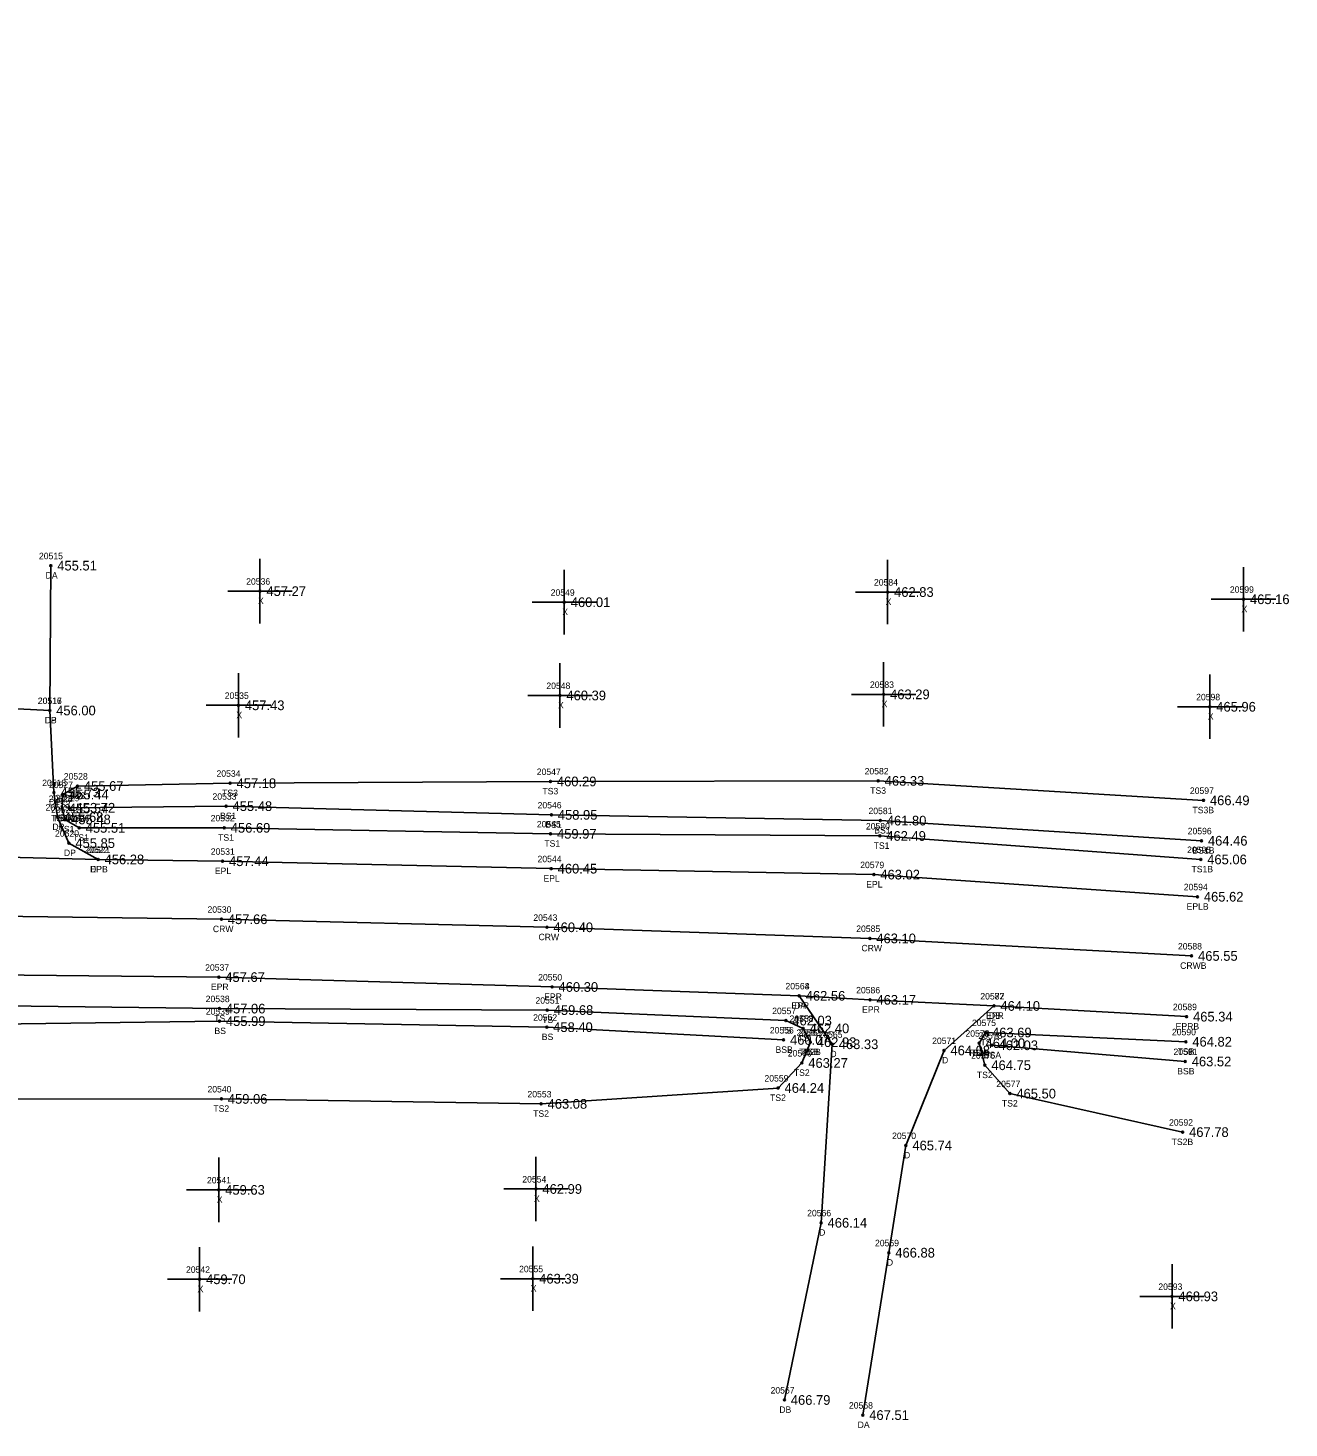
# Model space of a CAD drawing. Extents: x 1810114 to 1811498, y 790790 to 791824.
# Drawn here: x 1811302.7 to 1811498.2, y 791065.8 to 791282.8 of the extents above; entities that cross this region are included whole.
import ezdxf

# ---------------------------------------------------------------- set-up
doc = ezdxf.new("R2010")
doc.units = 0
for name, color, linetype in [('RD_DTM_BkLn1', 7, 'Continuous'), ('RD_DTM_BkLn2', 7, 'Continuous'), ('RD_DTM_BkLn_txCode', 7, 'Continuous'), ('RD_EX_Driveway', 7, 'Continuous'), ('RD_EX_Driveway_txCode', 7, 'Continuous'), ('RD_EX_Misc', 7, 'Continuous'), ('RD_EX_Misc_txCode', 7, 'Continuous'), ('RD_EX_Road', 7, 'Continuous'), ('RD_EX_Road_txCode', 7, 'Continuous'), ('RD_EX_TX_Driveway_ELEV', 7, 'Continuous'), ('RD_EX_TX_Misc_ELEV', 7, 'Continuous'), ('RD_EX_TX_Road_ELEV', 7, 'Continuous'), ('RD_HC_Survey_ELEV', 7, 'Continuous'), ('RD_HC_Survey_txCode', 7, 'Continuous'), ('RD_SMD_Locator', 7, 'Continuous')]:
    doc.layers.add(name, color=color, linetype=linetype)

msp = doc.modelspace()

# ---------------------------------------------------------------- linework, layer by layer
at = {"layer": 'RD_DTM_BkLn1'}
msp.add_lwpolyline([(1810803.51, 791274.51), (1810847.74, 791252.12), (1810893.26, 791230.1), (1810939.59, 791211.03), (1810986.75, 791193.39), (1811034.36, 791179.34), (1811083.17, 791167.31), (1811132.79, 791157.79), (1811182.67, 791151.51), (1811232.87, 791147.29), (1811282.59, 791145.39), (1811332.65, 791144.69), (1811383.13, 791143.44), (1811433.19, 791141.72), (1811483.07, 791139)], dxfattribs=at)
at = {"layer": 'RD_DTM_BkLn2'}
msp.add_line((1811452.12, 791125.15), (1811482.09, 791122.64), dxfattribs=at)
for points in [[(1811307.98, 791161.87), (1811308.04, 791164.02), (1811310.33, 791165.34), (1811334, 791165.77), (1811383.66, 791166.05), (1811434.49, 791166.14), (1811484.91, 791163.12)], [(1811307.98, 791161.87), (1811308.36, 791160.16), (1811310.61, 791158.85), (1811333.1, 791158.86), (1811383.68, 791157.93), (1811434.73, 791157.6), (1811484.49, 791153.96)], [(1811309.04, 791161.97), (1811333.38, 791162.22), (1811383.81, 791160.87), (1811434.81, 791159.98), (1811484.6, 791156.86)], [(1811170.77, 791135.26), (1811171.82, 791137.38), (1811175.07, 791138.52), (1811182.87, 791137.68), (1811232.22, 791132.55), (1811282.26, 791131.47), (1811332.33, 791130.84), (1811383.17, 791130.61), (1811420.16, 791128.98), (1811422.85, 791127.77), (1811423.96, 791125.63)], [(1811170.77, 791135.26), (1811170.4, 791132.25), (1811177.63, 791120.55), (1811182.15, 791120.82), (1811231.43, 791118.77), (1811282.72, 791116.78), (1811332.65, 791116.84), (1811382.22, 791116.07), (1811418.96, 791118.53), (1811422.64, 791122.41), (1811423.96, 791125.63)], [(1811172.12, 791135.15), (1811182.75, 791134.11), (1811232.21, 791129.55), (1811282.34, 791128.2), (1811332.35, 791128.89), (1811383.09, 791127.96), (1811419.81, 791125.98)], [(1811450.12, 791125.48), (1811451.13, 791127.13), (1811482.18, 791125.7)], [(1811450.12, 791125.48), (1811451.02, 791122.06), (1811454.9, 791117.66), (1811481.68, 791111.69)]]:
    msp.add_lwpolyline(points, dxfattribs=at)
at = {"layer": 'RD_EX_Driveway'}
msp.add_line((1811306.2, 791199.5), (1811306.03, 791177.05), dxfattribs=at)
for points in [[(1811285.25, 791154.67), (1811289.79, 791158.28), (1811291.76, 791160.78), (1811292, 791162.12), (1811291.93, 791177.79), (1811306.03, 791177.05), (1811306.69, 791164.33), (1811307.22, 791160.52), (1811309.01, 791156.49), (1811313.54, 791153.96)], [(1811422.24, 791132.82), (1811427.36, 791125.31), (1811425.63, 791097.64), (1811419.93, 791070.17)], [(1811432.09, 791067.83), (1811436.13, 791093), (1811438.78, 791109.62), (1811444.68, 791124.35), (1811452.43, 791131.25)]]:
    msp.add_lwpolyline(points, dxfattribs=at)
at = {"layer": 'RD_EX_Misc'}
for p, q in [((1811338.63, 791190.55), (1811338.63, 791200.55)), ((1811435.94, 791190.41), (1811435.94, 791200.41)), ((1811385.81, 791188.83), (1811385.81, 791198.83)), ((1811491.12, 791189.29), (1811491.12, 791199.29)), ((1811333.63, 791195.55), (1811343.63, 791195.55)), ((1811380.81, 791193.83), (1811390.81, 791193.83)), ((1811430.94, 791195.41), (1811440.94, 791195.41)), ((1811486.12, 791194.29), (1811496.12, 791194.29)), ((1811335.29, 791172.85), (1811335.29, 791182.85)), ((1811385.14, 791174.38), (1811385.14, 791184.38)), ((1811435.32, 791174.55), (1811435.32, 791184.55)), ((1811485.89, 791172.63), (1811485.89, 791182.63)), ((1811380.14, 791179.38), (1811390.14, 791179.38)), ((1811430.32, 791179.55), (1811440.32, 791179.55)), ((1811330.29, 791177.85), (1811340.29, 791177.85)), ((1811480.89, 791177.63), (1811490.89, 791177.63)), ((1811332.24, 791097.74), (1811332.24, 791107.74)), ((1811381.42, 791097.88), (1811381.42, 791107.88)), ((1811327.24, 791102.74), (1811337.24, 791102.74)), ((1811376.42, 791102.88), (1811386.42, 791102.88)), ((1811329.27, 791083.88), (1811329.27, 791093.88)), ((1811380.92, 791083.97), (1811380.92, 791093.97)), ((1811480.03, 791081.23), (1811480.03, 791091.23)), ((1811324.27, 791088.88), (1811334.27, 791088.88)), ((1811375.92, 791088.97), (1811385.92, 791088.97)), ((1811475.03, 791086.23), (1811485.03, 791086.23))]:
    msp.add_line(p, q, dxfattribs=at)
at = {"layer": 'RD_EX_Road'}
for points in [[(1810807.88, 791282.84), (1810852, 791259.68), (1810897.52, 791238.67), (1810942.78, 791219.24), (1810989.92, 791202.01), (1811037.03, 791187.9), (1811084.94, 791176.28), (1811134.78, 791167.28), (1811183.92, 791161.02), (1811232.9, 791156.58), (1811282.68, 791154.92), (1811285.25, 791154.67), (1811313.54, 791153.96), (1811332.83, 791153.68), (1811383.78, 791152.53), (1811433.81, 791151.61), (1811483.97, 791148.18)], [(1810799.46, 791266.97), (1810843.53, 791244.35), (1810889.8, 791222.88), (1810936.32, 791202.72), (1810983.79, 791185.28), (1811031.51, 791170.21), (1811081.62, 791158.02), (1811131.99, 791148.92), (1811148.3, 791146.24), (1811177.02, 791142.75), (1811182.52, 791142.23), (1811232.71, 791137.62), (1811281.86, 791136.25), (1811332.25, 791135.72), (1811383.92, 791134.19), (1811422.24, 791132.82), (1811433.21, 791132.2), (1811452.43, 791131.25), (1811482.29, 791129.59)]]:
    msp.add_lwpolyline(points, dxfattribs=at)
at = {"layer": 'RD_SMD_Locator'}
for centre in [(1811306.2, 791199.5), (1811338.63, 791195.55), (1811385.81, 791193.83), (1811435.94, 791195.41), (1811491.12, 791194.29), (1811385.14, 791179.38), (1811435.32, 791179.55), (1811306.03, 791177.05), (1811306.03, 791177.05), (1811335.29, 791177.85), (1811485.89, 791177.63), (1811310.33, 791165.34), (1811334, 791165.77), (1811383.66, 791166.05), (1811434.49, 791166.14), (1811306.69, 791164.33), (1811308.04, 791164.02), (1811307.98, 791161.87), (1811307.98, 791161.87), (1811309.04, 791161.97), (1811333.38, 791162.22), (1811484.91, 791163.12), (1811307.22, 791160.52), (1811308.36, 791160.16), (1811310.61, 791158.85), (1811333.1, 791158.86), (1811383.81, 791160.87), (1811434.81, 791159.98), (1811383.68, 791157.93), (1811434.73, 791157.6), (1811484.6, 791156.86), (1811309.01, 791156.49), (1811313.54, 791153.96), (1811313.54, 791153.96), (1811332.83, 791153.68), (1811383.78, 791152.53), (1811484.49, 791153.96), (1811433.81, 791151.61), (1811483.97, 791148.18), (1811332.65, 791144.69), (1811383.13, 791143.44), (1811433.19, 791141.72), (1811483.07, 791139), (1811332.25, 791135.72), (1811383.92, 791134.19), (1811422.24, 791132.82), (1811422.24, 791132.82), (1811332.33, 791130.84), (1811383.17, 791130.61), (1811433.21, 791132.2), (1811452.43, 791131.25), (1811452.43, 791131.25), (1811332.35, 791128.89), (1811420.16, 791128.98), (1811482.29, 791129.59), (1811383.09, 791127.96), (1811422.85, 791127.77), (1811451.13, 791127.13), (1811419.81, 791125.98), (1811423.96, 791125.63), (1811423.96, 791125.63), (1811427.36, 791125.31), (1811444.68, 791124.35), (1811450.12, 791125.48), (1811450.12, 791125.48), (1811452.12, 791125.15), (1811482.18, 791125.7), (1811422.64, 791122.41), (1811451.02, 791122.06), (1811482.09, 791122.64), (1811418.96, 791118.53), (1811454.9, 791117.66), (1811332.65, 791116.84), (1811382.22, 791116.07), (1811481.68, 791111.69), (1811438.78, 791109.62), (1811332.24, 791102.74), (1811381.42, 791102.88), (1811425.63, 791097.64), (1811436.13, 791093), (1811329.27, 791088.88), (1811380.92, 791088.97), (1811480.03, 791086.23), (1811419.93, 791070.17), (1811432.09, 791067.83)]:
    msp.add_circle(centre, 0.15, dxfattribs=at)

# ---------------------------------------------------------------- texts
at = {"layer": 'RD_DTM_BkLn_txCode'}
for s, p in [('20534', (1811331.89, 791166.77)), ('20547', (1811381.54, 791167.05)), ('20582', (1811432.37, 791167.14)), ('20527', (1811305.92, 791165.02)), ('20528', (1811308.21, 791166.34)), ('20523', (1811305.87, 791162.87)), ('20524', (1811305.87, 791162.87)), ('20529', (1811306.92, 791162.97)), ('TS3', (1811309.09, 791163.34)), ('20533', (1811331.27, 791163.22)), ('TS3', (1811332.76, 791163.77)), ('TS3', (1811382.42, 791164.05)), ('TS3', (1811433.24, 791164.14)), ('20597', (1811482.8, 791164.12)), ('20525', (1811306.24, 791161.16)), ('TS3', (1811306.79, 791162.02)), ('BS1', (1811332.44, 791160.22)), ('20546', (1811381.67, 791161.87)), ('20581', (1811432.97, 791160.98)), ('TS3B', (1811483.2, 791161.12)), ('TS3A', (1811306.25, 791159.87)), ('TS1A', (1811306.53, 791159.87)), ('TS1', (1811307.4, 791158.16)), ('BS1A', (1811307.61, 791159.97)), ('20526', (1811308.47, 791159.85)), ('20532', (1811330.98, 791159.86)), ('20545', (1811381.56, 791158.93)), ('BS1', (1811382.87, 791158.87)), ('20580', (1811432.57, 791158.6)), ('BS1', (1811433.86, 791157.98)), ('TS1', (1811309.65, 791156.85)), ('TS1', (1811332.14, 791156.86)), ('TS1', (1811382.72, 791155.93)), ('20596', (1811482.46, 791157.86)), ('TS1', (1811433.77, 791155.6)), ('20595', (1811482.37, 791154.96)), ('BS1B', (1811483.19, 791154.86)), ('TS1B', (1811483.05, 791151.96)), ('20538', (1811330.21, 791131.84)), ('20539', (1811330.23, 791129.89)), ('20551', (1811381.34, 791131.61)), ('20557', (1811418.04, 791129.98)), ('TS', (1811331.53, 791128.84)), ('20552', (1811380.98, 791128.96)), ('TS', (1811382.38, 791128.61)), ('20558', (1811420.73, 791128.77)), ('20575', (1811449.02, 791128.13)), ('BS', (1811331.57, 791126.89)), ('BS', (1811382.32, 791125.96)), ('20556', (1811417.67, 791126.98)), ('TS', (1811419.36, 791126.98)), ('20562', (1811421.82, 791126.63)), ('TS', (1811422.06, 791125.77)), ('20561', (1811422.1, 791126.63)), ('20573', (1811448, 791126.48)), ('20574', (1811448, 791126.48)), ('20578', (1811450.01, 791126.15)), ('20590', (1811480.02, 791126.7)), ('BSB', (1811418.56, 791123.98)), ('20560', (1811420.46, 791123.41)), ('TS2B', (1811422.24, 791123.63)), ('TSB', (1811422.69, 791123.63)), ('TS2A', (1811448.38, 791123.48)), ('TSA', (1811448.83, 791123.48)), ('TS', (1811450.34, 791125.13)), ('20591', (1811480.26, 791123.64)), ('TSB', (1811480.91, 791123.7)), ('20576', (1811448.88, 791123.06)), ('BSA', (1811450.86, 791123.15)), ('20559', (1811416.84, 791119.53)), ('TS2', (1811421.4, 791120.41)), ('TS2', (1811449.78, 791120.06)), ('BSB', (1811480.84, 791120.64)), ('20540', (1811330.49, 791117.84)), ('20553', (1811380.1, 791117.07)), ('20577', (1811452.79, 791118.66)), ('TS2', (1811331.4, 791114.84)), ('TS2', (1811417.71, 791116.53)), ('TS2', (1811453.66, 791115.66)), ('TS2', (1811380.98, 791114.07)), ('20592', (1811479.57, 791112.69)), ('TS2B', (1811479.97, 791109.69))]:
    msp.add_text(s, height=1, dxfattribs=at).set_placement(p)
at = {"layer": 'RD_EX_Driveway_txCode'}
for s, p in [('20515', (1811304.36, 791200.5)), ('DA', (1811305.4, 791197.5)), ('20516', (1811304.17, 791178.05)), ('20517', (1811304.2, 791178.05)), ('DB', (1811305.25, 791175.05)), ('DP', (1811305.25, 791175.05)), ('20518', (1811304.86, 791165.33)), ('DP', (1811305.91, 791162.33)), ('20519', (1811305.39, 791161.52)), ('DP', (1811306.44, 791158.52)), ('20520', (1811306.85, 791157.49)), ('DP', (1811308.23, 791154.49)), ('20521', (1811311.7, 791154.96)), ('DPB', (1811312.28, 791151.96)), ('20564', (1811420.1, 791133.82)), ('20572', (1811450.31, 791132.25)), ('DA', (1811421.45, 791130.82)), ('DB', (1811451.65, 791129.25)), ('20565', (1811425.22, 791126.31)), ('D', (1811427.06, 791123.31)), ('20571', (1811442.84, 791125.35)), ('D', (1811444.37, 791122.35)), ('20570', (1811436.63, 791110.62)), ('D', (1811438.48, 791107.62)), ('20566', (1811423.46, 791098.64)), ('D', (1811425.32, 791095.64)), ('20569', (1811433.98, 791094)), ('D', (1811435.82, 791091)), ('20567', (1811417.79, 791071.17)), ('DB', (1811419.15, 791068.17)), ('20568', (1811429.94, 791068.83)), ('DA', (1811431.29, 791065.83))]:
    msp.add_text(s, height=1, dxfattribs=at).set_placement(p)
at = {"layer": 'RD_EX_Misc_txCode'}
for s, p in [('20536', (1811336.49, 791196.55)), ('20584', (1811433.82, 791196.41)), ('20599', (1811489, 791195.29)), ('X', (1811338.32, 791193.55)), ('20549', (1811383.7, 791194.83)), ('X', (1811435.62, 791193.41)), ('X', (1811385.5, 791191.83)), ('X', (1811490.81, 791192.29)), ('20548', (1811383.03, 791180.38)), ('20583', (1811433.2, 791180.55)), ('20535', (1811333.17, 791178.85)), ('X', (1811435.01, 791177.55)), ('20598', (1811483.77, 791178.63)), ('X', (1811334.97, 791175.85)), ('X', (1811384.83, 791177.38)), ('X', (1811485.58, 791175.63)), ('20541', (1811330.41, 791103.74)), ('20554', (1811379.3, 791103.88)), ('X', (1811331.93, 791100.74)), ('X', (1811381.11, 791100.88)), ('20542', (1811327.16, 791089.88)), ('20555', (1811378.8, 791089.97)), ('X', (1811328.96, 791086.88)), ('X', (1811380.61, 791086.97)), ('20593', (1811477.91, 791087.23)), ('X', (1811479.72, 791084.23))]:
    msp.add_text(s, height=1, dxfattribs=at).set_placement(p)
at = {"layer": 'RD_EX_Road_txCode'}
for s, p in [('20522', (1811311.42, 791154.96)), ('20531', (1811331, 791154.68)), ('EPL', (1811312.33, 791151.96)), ('EPL', (1811331.63, 791151.68)), ('20544', (1811381.66, 791153.53)), ('20579', (1811431.69, 791152.61)), ('EPL', (1811382.58, 791150.53)), ('EPL', (1811432.61, 791149.61)), ('20594', (1811481.85, 791149.18)), ('EPLB', (1811482.29, 791146.18)), ('20537', (1811330.13, 791136.72)), ('20550', (1811381.76, 791135.19)), ('EPR', (1811331.02, 791133.72)), ('EPR', (1811382.69, 791132.19)), ('20563', (1811420.1, 791133.82)), ('20586', (1811431.06, 791133.2)), ('20587', (1811450.31, 791132.25)), ('EPR', (1811421.02, 791130.82)), ('EPR', (1811431.98, 791130.2)), ('20589', (1811480.17, 791130.59)), ('EPR', (1811451.2, 791129.25)), ('EPRB', (1811480.59, 791127.59))]:
    msp.add_text(s, height=1, dxfattribs=at).set_placement(p)
at = {"layer": 'RD_EX_TX_Driveway_ELEV'}
for s, p in [('455.51', (1811307.2, 791198.75)), ('456.00', (1811307.03, 791176.3)), ('456.00', (1811307.03, 791176.3)), ('455.73', (1811307.69, 791163.58)), ('455.68', (1811308.22, 791159.77)), ('455.85', (1811310.01, 791155.74)), ('456.28', (1811314.54, 791153.21)), ('462.56', (1811423.24, 791132.07)), ('464.10', (1811453.43, 791130.5)), ('463.33', (1811428.36, 791124.56)), ('464.08', (1811445.68, 791123.6)), ('465.74', (1811439.78, 791108.87)), ('466.14', (1811426.63, 791096.89)), ('466.88', (1811437.13, 791092.25)), ('466.79', (1811420.93, 791069.42)), ('467.51', (1811433.09, 791067.08))]:
    msp.add_text(s, height=1.5, dxfattribs=at).set_placement(p)
at = {"layer": 'RD_EX_TX_Misc_ELEV'}
for s, p in [('457.27', (1811339.63, 791194.8)), ('462.83', (1811436.94, 791194.66)), ('460.01', (1811386.81, 791193.08)), ('465.16', (1811492.12, 791193.54)), ('457.43', (1811336.29, 791177.1)), ('460.39', (1811386.14, 791178.63)), ('463.29', (1811436.32, 791178.8)), ('465.96', (1811486.89, 791176.88)), ('455.67', (1811311.33, 791164.59)), ('457.18', (1811335, 791165.02)), ('460.29', (1811384.66, 791165.3)), ('463.33', (1811435.49, 791165.39)), ('455.44', (1811309.04, 791163.27)), ('466.49', (1811485.91, 791162.37)), ('455.54', (1811308.98, 791161.12)), ('455.54', (1811308.98, 791161.12)), ('453.72', (1811310.04, 791161.22)), ('455.48', (1811334.38, 791161.47)), ('458.95', (1811384.81, 791160.12)), ('455.48', (1811309.36, 791159.41)), ('455.51', (1811311.61, 791158.1)), ('456.69', (1811334.1, 791158.11)), ('461.80', (1811435.81, 791159.23)), ('459.97', (1811384.68, 791157.18)), ('462.49', (1811435.73, 791156.85)), ('464.46', (1811485.6, 791156.11)), ('465.06', (1811485.49, 791153.21)), ('457.06', (1811333.33, 791130.09)), ('459.68', (1811384.17, 791129.86)), ('455.99', (1811333.35, 791128.14)), ('458.40', (1811384.09, 791127.21)), ('462.03', (1811421.16, 791128.23)), ('460.07', (1811420.81, 791125.23)), ('462.40', (1811423.85, 791127.02)), ('463.69', (1811452.13, 791126.38)), ('464.82', (1811483.18, 791124.95)), ('462.93', (1811424.96, 791124.88)), ('462.93', (1811424.96, 791124.88)), ('464.00', (1811451.12, 791124.73)), ('464.00', (1811451.12, 791124.73)), ('462.03', (1811453.12, 791124.4)), ('463.27', (1811423.64, 791121.66)), ('464.75', (1811452.02, 791121.31)), ('463.52', (1811483.09, 791121.89)), ('464.24', (1811419.96, 791117.78)), ('465.50', (1811455.9, 791116.91)), ('459.06', (1811333.65, 791116.09)), ('463.08', (1811383.22, 791115.32)), ('467.78', (1811482.68, 791110.94)), ('459.63', (1811333.24, 791101.99)), ('462.99', (1811382.42, 791102.13)), ('459.70', (1811330.27, 791088.13)), ('463.39', (1811381.92, 791088.22)), ('468.93', (1811481.03, 791085.48))]:
    msp.add_text(s, height=1.5, dxfattribs=at).set_placement(p)
at = {"layer": 'RD_EX_TX_Road_ELEV'}
for s, p in [('456.28', (1811314.54, 791153.21)), ('457.44', (1811333.83, 791152.93)), ('460.45', (1811384.78, 791151.78)), ('463.02', (1811434.81, 791150.86)), ('465.62', (1811484.97, 791147.43)), ('457.67', (1811333.25, 791134.97)), ('460.30', (1811384.92, 791133.44)), ('462.56', (1811423.24, 791132.07)), ('463.17', (1811434.21, 791131.45)), ('464.10', (1811453.43, 791130.5)), ('465.34', (1811483.29, 791128.84))]:
    msp.add_text(s, height=1.5, dxfattribs=at).set_placement(p)
at = {"layer": 'RD_HC_Survey_ELEV'}
for s, p in [('457.66', (1811333.65, 791143.94)), ('460.40', (1811384.13, 791142.69)), ('463.10', (1811434.19, 791140.97)), ('465.55', (1811484.07, 791138.25))]:
    msp.add_text(s, height=1.5, dxfattribs=at).set_placement(p)
at = {"layer": 'RD_HC_Survey_txCode'}
for s, p in [('20530', (1811330.49, 791145.69)), ('20543', (1811381.01, 791144.44)), ('CRW', (1811331.33, 791142.69)), ('CRW', (1811381.81, 791141.44)), ('20585', (1811431.07, 791142.72)), ('CRW', (1811431.88, 791139.72)), ('20588', (1811480.95, 791140)), ('CRWB', (1811481.29, 791137))]:
    msp.add_text(s, height=1, dxfattribs=at).set_placement(p)

doc.saveas('drawing.dxf')
